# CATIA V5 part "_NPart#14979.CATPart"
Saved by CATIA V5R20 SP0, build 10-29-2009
Part number: DIN6325 Ø4X35_Parallel Pin ISO 8734 - 4 x 35 - A - St
Revision: ANY
Definition: UNKNOWN
Nomenclature: DIN6325 Ø4X35_Parallel Pin ISO 8734 - 4 x 35 - A - St
Source: Unknown
Bounding box of the stored display mesh (mm): x 0 to 35, y -2 to 2, z -2 to 2
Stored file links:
  C:\Users\Utente\Desktop\IO LAVORO\3D X SITO CF\CUMSA\3D files AE\_NPart#14979.CATPart
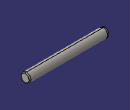
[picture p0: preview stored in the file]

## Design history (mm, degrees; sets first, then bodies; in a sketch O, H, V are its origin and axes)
Body1 "Base-Revolve" (main body)
  Solid1: solid without history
